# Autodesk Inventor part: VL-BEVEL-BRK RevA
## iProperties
Created: 2007-10
Part Number: VL-BEVEL-BRK RevA
Material: Steel
Document SubType Name: Modeling
Density: 7.85 g/cm^3
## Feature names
1. Base1
2. Extrusion1
3. Extrusion2
